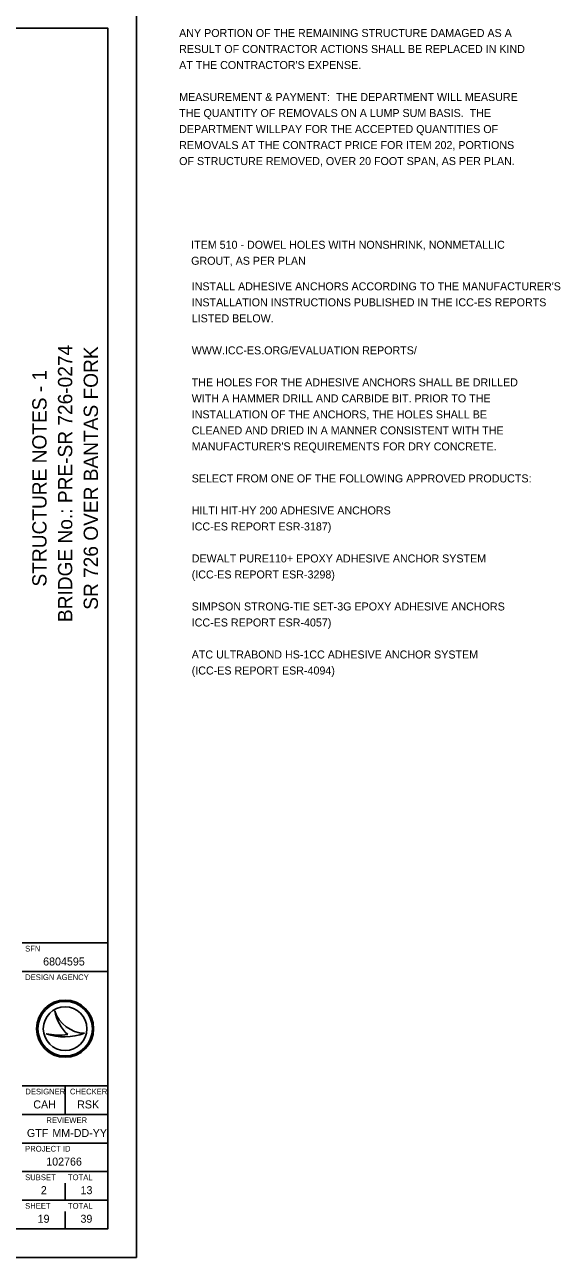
# Model space of a CAD drawing. Extents: x -15 to 144, y -80 to 40.
# Drawn here: x 32.04 to 41.42, y 0 to 21.56 of the extents above; entities that cross this region are included whole.
import ezdxf

# ---------------------------------------------------------------- set-up
doc = ezdxf.new("R2010")
doc.units = 0
for name, color, linetype in [('BR_P_Gen_Text', 7, 'Continuous'), ('SH_Border', 7, 'Continuous'), ('SH_Cut_Line', 7, 'Continuous'), ('SH_Data', 7, 'Continuous')]:
    doc.layers.add(name, color=color, linetype=linetype)

msp = doc.modelspace()

# ---------------------------------------------------------------- linework, layer by layer
at = {"layer": 'SH_Border'}
for p, q in [((32.567, 4.31), (32.567, 4.31)), ((32.417, 3.91), (32.417, 3.91)), ((32.75, 4), (32.75, 4)), ((33.087, 3.919), (33.087, 3.919)), ((32.75, 1), (32.75, 1.3)), ((32.375, 0.675), (32.375, 0.675)), ((32.75, 0.5), (32.75, 0.8))]:
    msp.add_line(p, q, dxfattribs=at)
for radius in [0.5, 0.477, 0.477, 0.382]:
    msp.add_circle((32.75, 4), radius, dxfattribs=at)
for centre, radius, start, end in [((33.116, 4.498), 0.58, 198.9257, 198.9319), ((33.347, 4.47), 0.796, 191.6379, 191.6421), ((33.116, 4.498), 0.58, 198.9319, 267.1657), ((33.347, 4.47), 0.796, 191.6421, 226.0947), ((32.739, 4.87), 1.013, 251.4576, 290.0832), ((32.648, 5.154), 1.266, 259.4964, 259.4995), ((32.739, 4.87), 1.013, 251.4527, 251.4576), ((32.648, 5.154), 1.266, 259.4995, 276.6672)]:
    msp.add_arc(centre, radius, start, end, dxfattribs=at)
at = {"layer": 'SH_Cut_Line'}
msp.add_lwpolyline([(0, 0), (34, 0), (34, 22), (0, 22)], close=True, dxfattribs=at)
at = {"layer": 'SH_Data'}
for p, q in [((32, 5.5), (33.5, 5.5)), ((32, 5), (33.5, 5)), ((32, 3), (33.5, 3)), ((32.75, 3), (32.75, 2.5)), ((32, 2.5), (33.5, 2.5)), ((32, 2), (33.5, 2)), ((32, 1.5), (33.5, 1.5)), ((32, 1), (33.5, 1))]:
    msp.add_line(p, q, dxfattribs=at)
msp.add_lwpolyline([(1.5, 21.5), (33.5, 21.5), (33.5, 0.5), (1.5, 0.5)], close=True, dxfattribs=at)

# ---------------------------------------------------------------- texts
at = {"layer": 'BR_P_Gen_Text'}
for s, p in [('ANY PORTION OF THE REMAINING STRUCTURE DAMAGED AS A ', (34.747, 21.346)), ('RESULT OF CONTRACTOR ACTIONS SHALL BE REPLACED IN KIND ', (34.747, 21.066)), ("AT THE CONTRACTOR'S EXPENSE.", (34.747, 20.786)), ('MEASUREMENT & PAYMENT:  THE DEPARTMENT WILL MEASURE ', (34.747, 20.226)), ('THE QUANTITY OF REMOVALS ON A LUMP SUM BASIS.  THE ', (34.747, 19.946)), ('DEPARTMENT WILLPAY FOR THE ACCEPTED QUANTITIES OF ', (34.747, 19.666)), ('REMOVALS AT THE CONTRACT PRICE FOR ITEM 202, PORTIONS ', (34.747, 19.386)), ('OF STRUCTURE REMOVED, OVER 20 FOOT SPAN, AS PER PLAN.', (34.747, 19.106)), ('ITEM 510 - DOWEL HOLES WITH NONSHRINK, NONMETALLIC ', (34.957, 17.642)), ('GROUT, AS PER PLAN', (34.957, 17.362)), ("INSTALL ADHESIVE ANCHORS ACCORDING TO THE MANUFACTURER'S", (34.967, 16.915)), ('INSTALLATION INSTRUCTIONS PUBLISHED IN THE ICC-ES REPORTS', (34.967, 16.635)), ('LISTED BELOW.', (34.967, 16.355)), ('WWW.ICC-ES.ORG/EVALUATION REPORTS/', (34.967, 15.795)), ('THE HOLES FOR THE ADHESIVE ANCHORS SHALL BE DRILLED', (34.967, 15.235)), ('WITH A HAMMER DRILL AND CARBIDE BIT. PRIOR TO THE', (34.967, 14.955)), ('INSTALLATION OF THE ANCHORS, THE HOLES SHALL BE', (34.967, 14.675)), ('CLEANED AND DRIED IN A MANNER CONSISTENT WITH THE', (34.967, 14.395)), ("MANUFACTURER'S REQUIREMENTS FOR DRY CONCRETE.", (34.967, 14.115)), ('SELECT FROM ONE OF THE FOLLOWING APPROVED PRODUCTS:', (34.967, 13.555)), ('HILTI HIT-HY 200 ADHESIVE ANCHORS', (34.967, 12.995)), ('ICC-ES REPORT ESR-3187)', (34.967, 12.715)), ('DEWALT PURE110+ EPOXY ADHESIVE ANCHOR SYSTEM', (34.967, 12.155)), ('(ICC-ES REPORT ESR-3298)', (34.967, 11.875)), ('SIMPSON STRONG-TIE SET-3G EPOXY ADHESIVE ANCHORS', (34.967, 11.315)), ('ICC-ES REPORT ESR-4057)', (34.967, 11.035)), ('ATC ULTRABOND HS-1CC ADHESIVE ANCHOR SYSTEM', (34.967, 10.475)), ('(ICC-ES REPORT ESR-4094)', (34.967, 10.195))]:
    msp.add_text(s, height=0.14, dxfattribs=at).set_placement(p)
at = {"layer": 'SH_Border'}
for s, p in [('BRIDGE No.: PRE-SR 726-0274', (32.875, 11.112)), ('SR 726 OVER BANTAS FORK', (33.325, 11.327)), ('STRUCTURE NOTES - 1', (32.425, 11.734))]:
    msp.add_text(s, height=0.25, rotation=90, dxfattribs=at).set_placement(p)
for s, height, p in [('SFN', 0.1, (32.05, 5.35)), ('6804595', 0.14, (32.365, 5.105)), ('DESIGN AGENCY', 0.1, (32.05, 4.85)), ('DESIGNER', 0.1, (32.054, 2.85)), ('CHECKER', 0.1, (32.835, 2.85)), ('CAH', 0.14, (32.193, 2.605)), ('RSK', 0.14, (32.961, 2.605)), ('REVIEWER', 0.1, (32.422, 2.35)), ('GTF', 0.14, (32.081, 2.105)), ('MM-DD-YY', 0.14, (32.527, 2.105)), ('PROJECT ID', 0.1, (32.05, 1.85)), ('102766', 0.14, (32.419, 1.605)), ('SUBSET', 0.1, (32.05, 1.35)), ('TOTAL', 0.1, (32.8, 1.35)), ('2', 0.14, (32.325, 1.105)), ('13', 0.14, (33.02, 1.105)), ('SHEET', 0.1, (32.05, 0.85)), ('TOTAL', 0.1, (32.8, 0.85)), ('19', 0.14, (32.269, 0.605)), ('39', 0.14, (33.019, 0.605))]:
    msp.add_text(s, height=height, dxfattribs=at).set_placement(p)

doc.saveas('drawing.dxf')
